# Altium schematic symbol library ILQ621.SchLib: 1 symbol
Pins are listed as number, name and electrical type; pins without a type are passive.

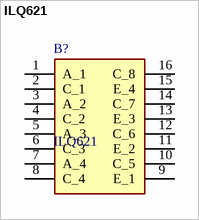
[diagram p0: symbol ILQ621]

## ILQ621
designator B?
Vishay Optocoupler ILQ621 Quad DC Input Transistor Output, 16-Pin PDIP, Through Hole; Geometry.Height: 4.7mm
footprint DIP762W56P254L1992H470Q16N
pins: 1 A_1, 2 C_1, 3 A_2, 4 C_2, 5 A_3, 6 C_3, 7 A_4, 8 C_4, 9 E_1, 10 C_5, 11 E_2, 12 C_6, 13 E_3, 14 C_7, 15 E_4, 16 C_8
